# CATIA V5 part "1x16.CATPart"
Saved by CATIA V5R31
Part number: 1x16
Definition: NONE
Nomenclature: 1
Source: Unknown
Description: PART-1-DESC
Bounding box of the stored display mesh (mm): x -64 to 64, y -4 to 4, z 0 to 10.5
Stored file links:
  C:\Users\super\Desktop\LEGO\TFG-2621\TFG_02621_anejos\1x16.CATPart
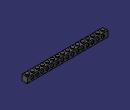
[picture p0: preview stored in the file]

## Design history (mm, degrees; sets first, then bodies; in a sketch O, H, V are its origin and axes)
AxisSystem1: origin (0, 0, 0), X (1, 0, 0), Y (0, 1, 0), Z (0, 0, 1)
Body1 "1" (main body)
  Solid1: solid without history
